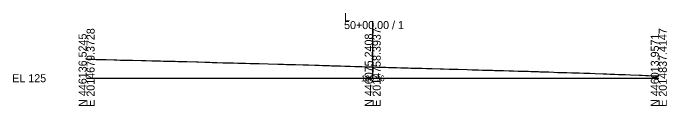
# Model space of a CAD drawing. Extents: x -26 to 4203, y -10 to 9526.
# Drawn here: x 3974.3 to 4202.8, y -9.7 to 22.8 of the extents above; entities that cross this region are included whole.
import ezdxf

# ---------------------------------------------------------------- set-up
doc = ezdxf.new("R2010")
doc.units = 0
for name, color, linetype in [('Default', 7, 'Continuous'), ('Exist Cross Section Cell', 7, 'Continuous'), ('Exist XS Center Line Elevation Label', 7, 'Continuous'), ('Exist XS Ground Line', 7, 'Continuous')]:
    doc.layers.add(name, color=color, linetype=linetype)

msp = doc.modelspace()

# ---------------------------------------------------------------- linework, layer by layer
at = {"layer": 'Exist Cross Section Cell'}
for p, q in [((4100, 0), (4100, 19.99)), ((4000, 0), (4100, 0)), ((4100, 0), (4200, 0))]:
    msp.add_line(p, q, dxfattribs=at)
at = {"layer": 'Exist XS Ground Line'}
msp.add_lwpolyline([(4000, 6.66), (4002.36, 6.61), (4003.37, 6.58), (4004.71, 6.55), (4006.79, 6.5), (4009.69, 6.43), (4010.07, 6.42), (4010.53, 6.41), (4011.85, 6.37), (4012.87, 6.35), (4014.61, 6.31), (4016.02, 6.27), (4019.18, 6.2), (4020.75, 6.16), (4022.8, 6.11), (4024.33, 6.07), (4025.51, 6.04), (4025.84, 6.03), (4026.94, 6.01), (4028.69, 5.96), (4030.97, 5.91), (4031.85, 5.89), (4035.01, 5.8), (4038.36, 5.71), (4039, 5.69), (4041.33, 5.63), (4042.16, 5.6), (4043.09, 5.57), (4043.88, 5.55), (4044.49, 5.53), (4045.67, 5.5), (4047.66, 5.44), (4049.25, 5.39), (4051.01, 5.35), (4051.34, 5.34), (4052.84, 5.3), (4053.98, 5.27), (4054.87, 5.24), (4055.49, 5.23), (4057.16, 5.19), (4059.49, 5.13), (4060.31, 5.1), (4063.5, 5.02), (4066.83, 4.92), (4067.59, 4.9), (4068.86, 4.86), (4069.82, 4.84), (4070.68, 4.81), (4071.8, 4.79), (4072.98, 4.75), (4075.75, 4.68), (4076.12, 4.67), (4077.52, 4.63), (4079.79, 4.56), (4081.31, 4.51), (4082.45, 4.48), (4083.11, 4.45), (4083.98, 4.43), (4084.92, 4.4), (4085.63, 4.38), (4086.71, 4.35), (4088.04, 4.32), (4088.79, 4.3), (4090.21, 4.25), (4092.07, 4.2), (4093.81, 4.15), (4095.11, 4.11), (4095.6, 4.09), (4096.26, 4.08), (4097.41, 4.04), (4098.29, 4.01), (4099.19, 3.98), (4100, 3.96), (4100.34, 3.95), (4101.45, 3.91), (4104.59, 3.82), (4105.56, 3.79), (4107.75, 3.72), (4108.35, 3.7), (4109.8, 3.66), (4110.92, 3.63), (4111.59, 3.62), (4112.45, 3.59), (4113.38, 3.57), (4114.1, 3.55), (4115.17, 3.52), (4116.59, 3.49), (4117.26, 3.47), (4118.77, 3.43), (4120.76, 3.37), (4123.59, 3.29), (4124.77, 3.26), (4126.76, 3.21), (4128.77, 3.15), (4129.9, 3.12), (4133.06, 3.03), (4134.75, 2.97), (4136.23, 2.93), (4136.54, 2.92), (4136.95, 2.9), (4138.34, 2.86), (4139.41, 2.84), (4140.13, 2.82), (4141.08, 2.8), (4141.92, 2.77), (4142.57, 2.75), (4143.72, 2.71), (4145.22, 2.68), (4145.73, 2.66), (4147.66, 2.6), (4148.86, 2.57), (4149.17, 2.56), (4150.79, 2.51), (4152.05, 2.48), (4152.6, 2.46), (4153.32, 2.44), (4154.4, 2.41), (4155.23, 2.39), (4156.19, 2.36), (4157.46, 2.32), (4157.98, 2.31), (4158.39, 2.29), (4159.76, 2.25), (4161.56, 2.18), (4163.31, 2.11), (4164.73, 2.05), (4165.1, 2.03), (4165.58, 2.02), (4167.89, 1.96), (4169.58, 1.92), (4170.4, 1.9), (4171.04, 1.88), (4172.22, 1.83), (4173.76, 1.79), (4174.23, 1.78), (4175.89, 1.72), (4177.79, 1.65), (4180.51, 1.54), (4181.81, 1.49), (4182.88, 1.45), (4183.68, 1.42), (4184.69, 1.38), (4185.93, 1.34), (4186.45, 1.32), (4186.87, 1.31), (4188.25, 1.25), (4190.07, 1.19), (4193.16, 1.07), (4194.09, 1.03), (4195.39, 0.99), (4196.37, 0.95), (4198.18, 0.89), (4199.5, 0.84), (4200, 0.82)], dxfattribs=at)

# ---------------------------------------------------------------- texts
at = {"layer": 'Default'}
msp.add_text('-', height=0.0001, dxfattribs=at).set_placement((4000, 0))
msp.add_text('-', height=0.0001, dxfattribs=at).set_placement((4000, 0))
at = {"layer": 'Exist Cross Section Cell'}
for s, p in [('L', (4090, 19.99)), ('50+00.00 / 1', (4090, 17.19)), ('EL 125', (3974, -1.4))]:
    msp.add_text(s, height=2.8, dxfattribs=at).set_placement(p)
for s, p in [('E 2014679.3728', (4002.8, -10)), ('E 2014758.3937', (4102.8, -10)), ('E 2014837.4147', (4202.8, -10)), ('N 446136.5245', (4000, -10)), ('N 446075.2408', (4100, -10)), ('N 446013.9571', (4200, -10))]:
    msp.add_text(s, height=2.8, rotation=90, dxfattribs=at).set_placement(p)
at = {"layer": 'Exist XS Center Line Elevation Label'}
msp.add_text('128.96', height=2, dxfattribs=at).set_placement((4095.97, -1.04))

doc.saveas('drawing.dxf')
